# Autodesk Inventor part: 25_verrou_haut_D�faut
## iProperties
Created: 2011-01
Part Number: 25_verrou_haut_D�faut
Document SubType Name: Modeling
Designer: eric
Density: 1 g/cm^3
Mass: 9.60647 g
Surface Area: 107.796 cm^2
Volume: 9.60647 cm^3
Author: eric
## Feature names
1. Extrusion1
2. Base1
